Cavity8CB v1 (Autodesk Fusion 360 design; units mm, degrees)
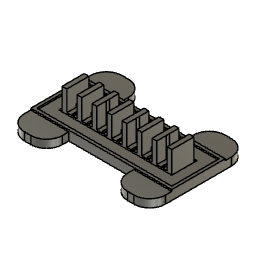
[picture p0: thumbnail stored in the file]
sketch "Sketch1" plane through (0, 0, 0) normal (0, 0, 1) x axis (1, 0, 0)
  line L1 (3, 0) -> (0, 0)
  line L2 (3, 14) -> (3, 0)
  line L3 (0, 14) -> (3, 14)
  line L4 (0, 0) -> (0, 14)
  line L5 (9.5, 14) -> (3, 14)
  line L6 (9.5, 0) -> (9.5, 14)
  line L7 (3, 0) -> (9.5, 0)
  line L8 (9.5, 8) -> (3, 8)
  line L9 (9.5, 6) -> (9.5, 8)
  line L10 (3, 6) -> (9.5, 6)
  line L11 (3, 8) -> (3, 6)
  line L12 (7, 0.7) -> (5.5, 0.7)
  line L13 (7, 5.5) -> (7, 0.7)
  line L14 (5.5, 5.5) -> (7, 5.5)
  line L15 (5.5, 0.7) -> (5.5, 5.5)
  line L16 (12.5, 0) -> (9.5, 0)
  line L17 (12.5, 14) -> (12.5, 0)
  line L18 (9.5, 14) -> (12.5, 14)
  line L19 (9.5, 0) -> (9.5, 14)
  line L20 (19, 14) -> (12.5, 14)
  line L21 (19, 0) -> (19, 14)
  line L22 (12.5, 0) -> (19, 0)
  line L23 (19, 8) -> (12.5, 8)
  line L24 (19, 6) -> (19, 8)
  line L25 (12.5, 6) -> (19, 6)
  line L26 (12.5, 6) -> (12.5, 8)
  line L27 (16.5, 5.5) -> (15, 5.5)
  line L28 (16.5, 0.7) -> (16.5, 5.5)
  line L29 (15, 0.7) -> (16.5, 0.7)
  line L30 (15, 5.5) -> (15, 0.7)
  line L31 (22, 14) -> (19, 14)
  line L32 (22, 0) -> (22, 14)
  line L33 (19, 0) -> (22, 0)
  line L34 (19, 14) -> (19, 0)
  line L35 (28.5, 14) -> (22, 14)
  line L36 (28.5, 0) -> (28.5, 14)
  line L37 (22, 0) -> (28.5, 0)
  line L38 (28.5, 8) -> (22, 8)
  line L39 (28.5, 6) -> (28.5, 8)
  line L40 (22, 6) -> (28.5, 6)
  line L41 (22, 8) -> (22, 6)
  line L42 (31.5, 14) -> (28.5, 14)
  line L43 (31.5, 0) -> (31.5, 14)
  line L44 (28.5, 0) -> (31.5, 0)
  line L45 (28.5, 14) -> (28.5, 0)
  line L46 (26, 5.5) -> (24.5, 5.5)
  line L47 (26, 0.7) -> (26, 5.5)
  line L48 (24.5, 0.7) -> (26, 0.7)
  line L49 (24.5, 5.5) -> (24.5, 0.7)
  line L50 (38, 14) -> (31.5, 14)
  line L51 (38, 0) -> (38, 14)
  line L52 (31.5, 0) -> (38, 0)
  line L53 (38, 8) -> (31.5, 8)
  line L54 (38, 6) -> (38, 8)
  line L55 (31.5, 6) -> (38, 6)
  line L56 (31.5, 8) -> (31.5, 6)
  line L57 (35.5, 5.5) -> (34, 5.5)
  line L58 (35.5, 0.7) -> (35.5, 5.5)
  line L59 (34, 0.7) -> (35.5, 0.7)
  line L60 (34, 5.5) -> (34, 0.7)
  line L61 (41, 14) -> (38, 14)
  line L62 (41, 0) -> (41, 14)
  line L63 (38, 0) -> (41, 0)
  line L64 (38, 14) -> (38, 0)
  line L65 (47.5, 14) -> (41, 14)
  line L66 (47.5, 0) -> (47.5, 14)
  line L67 (41, 0) -> (47.5, 0)
  line L68 (47.5, 8) -> (41, 8)
  line L69 (47.5, 6) -> (47.5, 8)
  line L70 (41, 6) -> (47.5, 6)
  line L71 (41, 8) -> (41, 6)
  line L72 (45, 5.5) -> (43.5, 5.5)
  line L73 (45, 0.7) -> (45, 5.5)
  line L74 (43.5, 0.7) -> (45, 0.7)
  line L75 (43.5, 5.5) -> (43.5, 0.7)
  line L76 (50.5, 14) -> (47.5, 14)
  line L77 (50.5, 0) -> (50.5, 14)
  line L78 (47.5, 0) -> (50.5, 0)
  line L79 (47.5, 14) -> (47.5, 0)
  line L80 (57, 14) -> (50.5, 14)
  line L81 (57, 0) -> (57, 14)
  line L82 (50.5, 0) -> (57, 0)
  line L83 (57, 8) -> (50.5, 8)
  line L84 (57, 6) -> (57, 8)
  line L85 (50.5, 6) -> (57, 6)
  line L86 (50.5, 8) -> (50.5, 6)
  line L87 (54.5, 5.5) -> (53, 5.5)
  line L88 (54.5, 0.7) -> (54.5, 5.5)
  line L89 (53, 0.7) -> (54.5, 0.7)
  line L90 (53, 5.5) -> (53, 0.7)
  line L91 (60, 14) -> (57, 14)
  line L92 (60, 0) -> (60, 14)
  line L93 (57, 0) -> (60, 0)
  line L94 (57, 14) -> (57, 0)
  line L95 (66.5, 14) -> (60, 14)
  line L96 (66.5, 0) -> (66.5, 14)
  line L97 (60, 0) -> (66.5, 0)
  line L98 (66.5, 8) -> (60, 8)
  line L99 (66.5, 6) -> (66.5, 8)
  line L100 (60, 6) -> (66.5, 6)
  line L101 (60, 8) -> (60, 6)
  line L102 (64, 5.5) -> (62.5, 5.5)
  line L103 (64, 0.7) -> (64, 5.5)
  line L104 (62.5, 0.7) -> (64, 0.7)
  line L105 (62.5, 5.5) -> (62.5, 0.7)
  line L106 (69.5, 14) -> (66.5, 14)
  line L107 (69.5, 0) -> (69.5, 14)
  line L108 (66.5, 0) -> (69.5, 0)
  line L109 (66.5, 14) -> (66.5, 0)
  line L110 (74, 7) -> (-10, 7)
  line L111 (5.5, 8.5) -> (7, 8.5)
  line L112 (5.5, 13.3) -> (5.5, 8.5)
  line L113 (7, 13.3) -> (5.5, 13.3)
  line L114 (7, 8.5) -> (7, 13.3)
  line L115 (15, 8.5) -> (15, 13.3)
  line L116 (16.5, 8.5) -> (15, 8.5)
  line L117 (16.5, 13.3) -> (16.5, 8.5)
  line L118 (15, 13.3) -> (16.5, 13.3)
  line L119 (24.5, 13.3) -> (26, 13.3)
  line L120 (24.5, 8.5) -> (24.5, 13.3)
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  point P1 (0, 0)
  point P2 (0, 0)
  point P8 (3, 8)
  point P9 (9.5, 8)
  point P11 (3, 6)
  point P21 (12.5, 8)
  point P22 (19, 8)
  point P23 (19, 6)
  point P24 (19, 6)
  point P25 (12.5, 6)
  point P35 (22, 8)
  point P36 (28.5, 8)
  point P37 (28.5, 6)
  point P38 (22, 6)
  point P48 (31.5, 8)
  point P49 (38, 8)
  point P50 (38, 6)
  point P51 (31.5, 6)
  point P61 (41, 8)
  point P62 (47.5, 8)
  point P63 (47.5, 6)
  point P64 (41, 6)
  point P74 (50.5, 8)
  point P75 (57, 8)
  point P76 (57, 6)
  point P77 (50.5, 6)
  point P87 (60, 8)
  point P88 (66.5, 8)
  point P89 (66.5, 6)
  point P90 (60, 6)
  point P12 (5.5, 0.7)
  point P102 (5.5, 13.3)
  point P13 (7, 0.7)
  point P103 (7, 13.3)
  point P14 (7, 5.5)
  point P100 (7, 8.5)
  point P15 (5.5, 5.5)
  point P101 (5.5, 8.5)
  point P26 (15, 5.5)
  point P105 (15, 8.5)
  point P27 (16.5, 5.5)
  point P106 (16.5, 8.5)
  point P28 (16.5, 0.7)
  point P107 (16.5, 13.3)
  point P29 (15, 0.7)
  point P104 (15, 13.3)
  point P42 (24.5, 5.5)
  point P110 (24.5, 8.5)
  point P43 (26, 5.5)
  point P111 (26, 8.5)
  point P44 (26, 0.7)
  point P108 (26, 13.3)
  point P45 (24.5, 0.7)
  point P109 (24.5, 13.3)
  point P52 (34, 5.5)
  point P112 (34, 8.5)
  point P53 (35.5, 5.5)
  point P113 (35.5, 8.5)
  point P54 (35.5, 0.7)
  point P115 (35.5, 13.3)
  point P55 (34, 0.7)
  point P114 (34, 13.3)
  point P65 (43.5, 5.5)
  point P118 (43.5, 8.5)
  point P66 (45, 5.5)
  point P119 (45, 8.5)
  point P67 (45, 0.7)
  point P116 (45, 13.3)
  point P68 (43.5, 0.7)
  point P117 (43.5, 13.3)
  point P78 (53, 5.5)
  point P120 (53, 8.5)
  point P79 (54.5, 5.5)
  point P121 (54.5, 8.5)
  point P80 (54.5, 0.7)
  point P123 (54.5, 13.3)
  point P81 (53, 0.7)
  point P122 (53, 13.3)
  point P91 (62.5, 5.5)
  point P124 (62.5, 8.5)
  point P92 (64, 5.5)
  point P125 (64, 8.5)
  point P93 (64, 0.7)
  point P127 (64, 13.3)
  point P94 (62.5, 0.7)
  point P126 (62.5, 13.3)
  point P132 (0, 0)
  point P3 (3, 0)
  point P5 (0, 14)
  point P4 (3, 14)
  point P6 (9.5, 14)
  point P10 (9.5, 6)
  point P7 (9.5, 0)
  point P16 (12.5, 0)
  point P17 (12.5, 14)
  point P19 (19, 14)
  point P30 (22, 14)
  point P33 (28.5, 14)
  point P39 (31.5, 14)
  point P41 (28.5, 0)
  point P46 (38, 14)
  point P56 (41, 14)
  point P58 (38, 0)
  point P59 (47.5, 14)
  point P69 (50.5, 14)
  point P71 (47.5, 0)
  point P72 (57, 14)
  point P82 (60, 14)
  point P84 (57, 0)
  point P85 (66.5, 14)
  point P95 (69.5, 14)
  point P97 (66.5, 0)
  horizontal L1
  vertical L2
  horizontal L3
  vertical L4
  coincident P1 P2
  perpendicular L2 L5
  perpendicular L3 L6
  perpendicular L2 L7
  coincident L2 P8
  coincident L6 P9
  perpendicular L6 L8
  perpendicular L8 L9
  coincident L2 P11
  perpendicular L2 L10
  horizontal L12
  vertical L13
  horizontal L14
  vertical L15
  horizontal L16
  vertical L17
  horizontal L18
  vertical L19
  perpendicular L17 L20
  perpendicular L18 L21
  perpendicular L17 L22
  coincident L17 P21
  coincident L21 P22
  perpendicular L21 L23
  coincident L21 P23
  coincident L21 P24
  coincident L17 P25
  perpendicular L17 L25
  horizontal L27
  vertical L28
  horizontal L29
  vertical L30
  horizontal L31
  vertical L32
  horizontal L33
  vertical L34
  perpendicular L32 L35
  perpendicular L35 L36
  perpendicular L32 L37
  coincident L32 P35
  coincident L36 P36
  perpendicular L36 L38
  coincident L36 P37
  coincident L32 P38
  perpendicular L32 L40
  horizontal L42
  vertical L43
  horizontal L44
  vertical L45
  horizontal L46
  vertical L47
  horizontal L48
  vertical L49
  perpendicular L43 L50
  perpendicular L50 L51
  coincident L43 P48
  coincident L51 P49
  perpendicular L51 L53
  coincident L51 P50
  coincident L43 P51
  perpendicular L43 L55
  horizontal L57
  vertical L58
  horizontal L59
  vertical L60
  horizontal L61
  vertical L62
  horizontal L63
  vertical L64
  perpendicular L62 L65
  perpendicular L65 L66
  coincident L62 P61
  coincident L66 P62
  perpendicular L66 L68
  coincident L66 P63
  coincident L62 P64
  perpendicular L62 L70
  horizontal L72
  vertical L73
  horizontal L74
  vertical L75
  horizontal L76
  vertical L77
  horizontal L78
  vertical L79
  perpendicular L77 L80
  perpendicular L76 L81
  coincident L77 P74
  coincident L81 P75
  perpendicular L81 L83
  coincident L81 P76
  coincident L77 P77
  perpendicular L77 L85
  horizontal L87
  vertical L88
  horizontal L89
  vertical L90
  horizontal L91
  vertical L92
  horizontal L93
  vertical L94
  perpendicular L92 L95
  perpendicular L95 L96
  coincident L92 P87
  coincident L96 P88
  perpendicular L96 L98
  coincident L96 P89
  coincident L92 P90
  perpendicular L92 L100
  horizontal L102
  vertical L103
  horizontal L104
  vertical L105
  horizontal L106
  vertical L107
  horizontal L108
  vertical L109
  perpendicular L107 L110
  symmetric P12 L110 P102
  symmetric P13 L110 P103
  symmetric P14 L110 P100
  symmetric P15 L110 P101
  symmetric P26 L110 P105
  symmetric P27 L110 P106
  symmetric P28 L110 P107
  symmetric P29 L110 P104
  symmetric P42 L110 P110
  symmetric P43 L110 P111
  symmetric P44 L110 P108
  symmetric P45 L110 P109
  symmetric P52 L110 P112
  symmetric P53 L110 P113
  symmetric P54 L110 P115
  symmetric P55 L110 P114
  symmetric P65 L110 P118
  symmetric P66 L110 P119
  symmetric P67 L110 P116
  symmetric P68 L110 P117
  symmetric P78 L110 P120
  symmetric P79 L110 P121
  symmetric P80 L110 P123
  symmetric P81 L110 P122
  symmetric P91 L110 P124
  symmetric P92 L110 P125
  symmetric P93 L110 P127
  symmetric P94 L110 P126
  coincident P1 P132
  dimension "d1" distance P2 P3 = 3
  dimension "d2" distance P2 P5 = 14
  dimension "d3" distance P4 P6 = 6.5
  dimension "d4" distance L5 L8 = 6
  dimension "d5" distance P9 P10 = 2
  dimension "d6" distance L10 L14 = 0.5
  dimension "d7" distance L7 L12 = 0.7
  dimension "d8" distance L2 L15 = 2.5
  dimension "d9" distance L6 L13 = 2.5
  dimension "d10" distance P7 P16 = 3
  dimension "d11" distance P17 P19 = 6.5
  dimension "d12" distance L25 L27 = 0.5
  dimension "d13" distance L22 L29 = 0.7
  dimension "d14" distance L21 L28 = 2.5
  dimension "d15" distance L17 L30 = 2.5
  dimension "d16" distance P19 P30 = 3
  dimension "d17" distance P30 P33 = 6.5
  dimension "d18" distance P33 P39 = 3
  dimension "d19" distance P33 P41 = 14
  dimension "d20" distance L40 L46 = 0.5
  dimension "d21" distance L37 L48 = 0.7
  dimension "d22" distance L36 L47 = 2.5
  dimension "d23" distance L32 L49 = 2.5
  dimension "d24" distance P39 P46 = 6.5
  dimension "d25" distance P46 P56 = 3
  dimension "d26" distance P46 P58 = 14
  dimension "d27" distance L55 L57 = 0.5
  dimension "d28" distance L52 L59 = 0.7
  dimension "d29" distance L58 L64 = 2.5
  dimension "d30" distance L43 L60 = 2.5
  dimension "d31" distance P56 P59 = 6.5
  dimension "d32" distance P59 P69 = 3
  dimension "d33" distance P59 P71 = 14
  dimension "d34" distance L70 L72 = 0.5
  dimension "d35" distance L67 L74 = 0.7
  dimension "d36" distance L62 L75 = 2.5
  dimension "d37" distance L66 L73 = 2.5
  dimension "d38" distance P72 P82 = 3
  dimension "d39" distance P72 P84 = 14
  dimension "d40" distance L85 L87 = 0.5
  dimension "d41" distance L82 L89 = 0.7
  dimension "d42" distance L77 L90 = 2.5
  dimension "d43" distance L88 L94 = 2.5
  dimension "d44" distance P82 P85 = 6.5
  dimension "d45" distance P85 P95 = 3
  dimension "d46" distance P85 P97 = 14
  dimension "d47" distance L100 L102 = 0.5
  dimension "d48" distance L97 L104 = 0.7
  dimension "d49" distance L92 L105 = 2.5
  dimension "d50" distance L103 L109 = 2.5
  dimension "d51" distance L5 L110 = 7
  dimension "d52" = 1
  dimension "d53" distance = 7
  dimension "d54" distance = 7
  dimension "d55" distance = 7
  dimension "d56" distance = 7
  dimension "d57" = 1.9
extrude "Extrude1" new body sketch "Sketch1" against normal blind 5
extrude "Extrude2" cut sketch "Sketch1" against normal blind 1
extrude "Extrude3" add sketch "Sketch1" profile of L2 L6 L8 L9 L10 L11 L17 L19 L21 L23 L24 L25 L26 L32 L34 L36 L38 L39 L40 L41 L43 L45 L51 L53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 along normal blind 2
extrude "Extrude4" add sketch "Sketch1" along normal blind 13 and against normal blind 1
extrude "Extrude5" add sketch "Sketch1" along normal blind 1
sketch "Sketch2" plane through (0, -9.9, 0) normal (0, -1, 0) x axis (1, 0, 0)
  line L1 (-9.9, -5) -> (-9.9, 1)
  line L2 (79.4, -5) -> (-9.9, -5)
  line L3 (79.4, 1) -> (79.4, -5)
  line L4 (-9.9, 1) -> (79.4, 1)
  line L5 (14.1, -5) -> (-9.9, -5)
  line L6 (14.1, 0) -> (14.1, -5)
  line L7 (-9.9, 0) -> (14.1, 0)
  line L8 (-9.9, -5) -> (-9.9, 0)
  line L9 (55.4, -5) -> (79.4, -5)
  line L10 (55.4, 0) -> (55.4, -5)
  line L11 (79.4, 0) -> (55.4, 0)
  line L12 (79.4, -5) -> (79.4, 0)
  point P3 (-9.9, -5)
  point P6 (-9.9, -5)
  point P4 (79.4, -5)
  point P10 (79.4, -5)
  point P7 (14.1, -5)
  point P9 (-9.9, 0)
  point P11 (55.4, -5)
  point P13 (79.4, 0)
  horizontal L5
  vertical L6
  horizontal L7
  vertical L8
  coincident P3 P6
  horizontal L9
  vertical L10
  horizontal L11
  vertical L12
  coincident P4 P10
  dimension "d70" distance P6 P7 = 24
  dimension "d71" distance P6 P9 = 5
  dimension "d72" distance P10 P11 = 24
  dimension "d73" distance P10 P13 = 5
extrude "Extrude6" add sketch "Sketch2" profile of L1 L2 L3 L5 L6 L7 L8 L9 L10 L11 L12 along normal blind 14
fillet "Fillet1" radius 10
sketch "Sketch3" plane through (0, 23.9, 0) normal (0, 1, 0) x axis (-1, 0, 0)
  line L1 (-79.4, -5) -> (-79.4, 1)
  line L2 (9.9, -5) -> (-79.4, -5)
  line L3 (9.9, 1) -> (9.9, -5)
  line L4 (-79.4, 1) -> (9.9, 1)
  line L5 (-55.4, -5) -> (-79.4, -5)
  line L6 (-55.4, 0) -> (-55.4, -5)
  line L7 (-79.4, 0) -> (-55.4, 0)
  line L8 (-79.4, -5) -> (-79.4, 0)
  line L9 (-14.1, -5) -> (9.9, -5)
  line L10 (-14.1, 0) -> (-14.1, -5)
  line L11 (9.9, 0) -> (-14.1, 0)
  line L12 (9.9, -5) -> (9.9, 0)
  point P3 (-79.4, -5)
  point P6 (-79.4, -5)
  point P4 (9.9, -5)
  point P10 (9.9, -5)
  point P7 (-55.4, -5)
  point P9 (-79.4, 0)
  point P11 (-14.1, -5)
  point P13 (9.9, 0)
  horizontal L5
  vertical L6
  horizontal L7
  vertical L8
  coincident P3 P6
  horizontal L9
  vertical L10
  horizontal L11
  vertical L12
  coincident P4 P10
  dimension "d78" distance P6 P7 = 24
  dimension "d79" distance P6 P9 = 5
  dimension "d80" distance P10 P11 = 24
  dimension "d81" distance P10 P13 = 5
extrude "Extrude7" add sketch "Sketch3" profile of L1 L2 L3 L5 L6 L7 L8 L9 L10 L11 L12 along normal blind 14
fillet "Fillet2" radius 10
